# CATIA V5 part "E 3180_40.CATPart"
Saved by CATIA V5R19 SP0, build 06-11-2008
Nomenclature: E 3180_40
Description: PART-E 3180_40-DESC
Property "Hersteller": "Meusburger"
Property "Material": "2.0598 180 HB / Graphit _ graphite"
Property "Bestellnummer": "E 3180/40"
Property "Teilenummer": "E 3180/40"
Property "Beschreibung": "Gleitplatte lang wartungsfrei _ Long self-lubricating flat guiding stock"
Material "Brass": density 8216 kg/m3, Young's modulus 1.31e+11 Pa, Poisson ratio 0.35, thermal expansion 1.67e-05 1/K
Bounding box of the stored display mesh (mm): x -20.5 to 19.5, y 0 to 6, z 0 to 500
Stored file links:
  G:\UTB\Kombinované\Bakalářská práce\Catia\FORMA\E 3180_40.CATPart
  D:\Aplikace\CATIA\Nová složka\win_b64\startup\materials\Catalog.CATMaterial
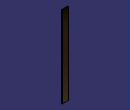
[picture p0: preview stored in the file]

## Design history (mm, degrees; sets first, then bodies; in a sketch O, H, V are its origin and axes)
Body1 "E 3180_40" (main body)
  Solid1: solid without history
